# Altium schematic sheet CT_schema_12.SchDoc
size 382 x 278 mm
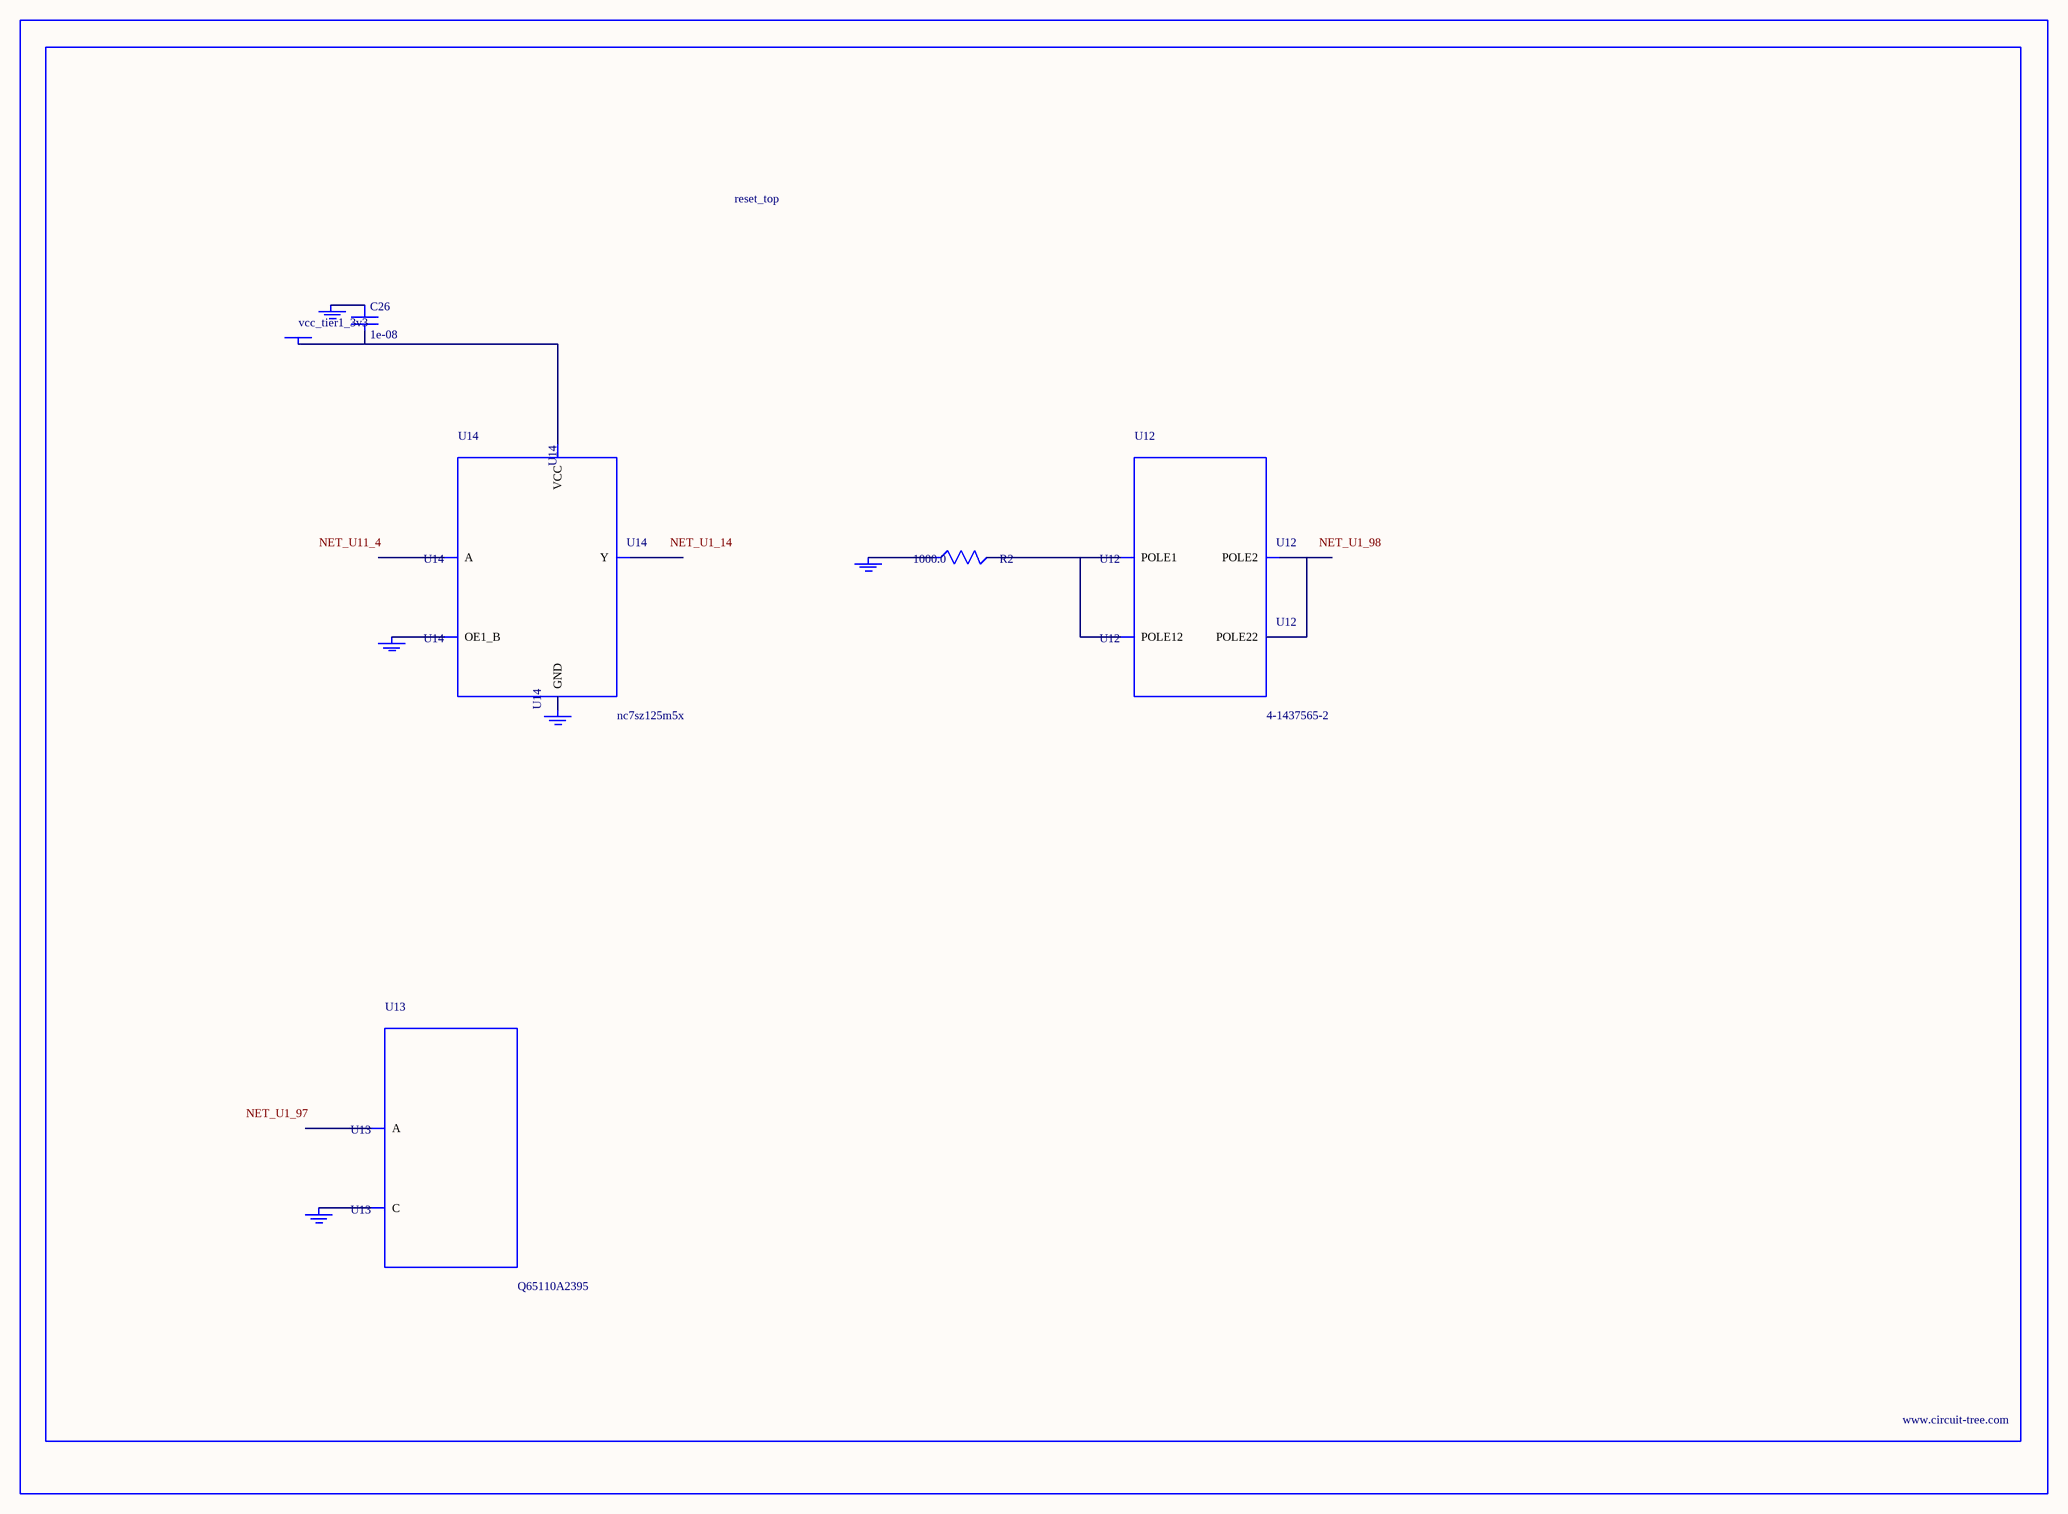
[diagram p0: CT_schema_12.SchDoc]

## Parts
BORDER11  (no value)
C26  1e-08  [C0402]
GND_INSTANCE_11_0  (no value)
GND_INSTANCE_11_1  (no value)
GND_INSTANCE_11_2  (no value)
GND_INSTANCE_11_3  (no value)
GND_INSTANCE_11_4  (no value)
POWER_INSTANCE_11_0  vcc_tier1_3v3
R2  1000.0  [R0603]
U12  4-1437565-2  [SW_4-1437565-2]
U13  Q65110A2395  [LGM67K-G1J2-24-Z]
U14  nc7sz125m5x  [NC7SZ125M5X]

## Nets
NetC26_1: C26.1 GND_INSTANCE_11_2.0(GND)
NetC26_2: C26.2 POWER_INSTANCE_11_0.0(PWR) U14.5(VCC)
NetGND_INSTANCE_11_0_0: GND_INSTANCE_11_0.0(GND) R2.1
NetGND_INSTANCE_11_1_0: GND_INSTANCE_11_1.0(GND) U13.C
NetGND_INSTANCE_11_3_0: GND_INSTANCE_11_3.0(GND) U14.1(OE1_B)
NetGND_INSTANCE_11_4_0: GND_INSTANCE_11_4.0(GND) U14.3(GND)
NetR2_2: R2.2 U12.1(POLE1) U12.2(POLE12)
NetU12_3: U12.3(POLE2) U12.4(POLE22)

Not connected (* = marked no-connect by the designer): U13 A; U14 2(A) 4(Y)

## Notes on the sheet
- Labels drawn without touching a wire or pin: NET_U1_14, NET_U1_97, NET_U1_98, NET_U11_4

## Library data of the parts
BORDER11 = BORDER_PAGE11
C26 = C0402C103K3RAC
GND_INSTANCE_11_0-GND_INSTANCE_11_4 = GND
POWER_INSTANCE_11_0 = PWR
R2 = RC0603JR-071KL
